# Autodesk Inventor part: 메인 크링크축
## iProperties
Manager: KYOUNG IL JANG
Company: 한국ATC센터
Created: 2012-10
Part Number: 메인 크링크축
Document SubType Name: Modeling
Density: 1 g/cm^3
Checked By: KYOUNG IL JANG
Vendor: CBT Solutions
Designer: KYOUNG IL JANG
크링크폭: 19.000 mm
크랭크길이: 18.000 mm
크랭키위치: 65.000 mm
무게추: 90.000 mm
크랭크각도높이: 21.000 mm
크링크각도: -15.00 deg
Author: KYOUNG IL JANG
